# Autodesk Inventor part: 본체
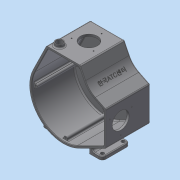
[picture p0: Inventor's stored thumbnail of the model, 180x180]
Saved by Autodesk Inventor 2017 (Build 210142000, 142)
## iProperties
Created: 2017-05
Part Number: 본체
Material: 알루미늄 6061
Document SubType Name: Modeling
Designer: mduedu
Density: 2.71 g/cm^3
Mass: 1345.72 g
Surface Area: 1824.08 cm^2
Volume: 496.576 cm^3
Appearance: 기본값
Author: mduedu
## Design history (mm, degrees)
sketch "스케치1"
  geometry: L1 (-71.801, 35.28)-(-40, 100); L2 (-40, 100)-(40, 100); L3 (40, 100)-(59.768, 59.768); L4 (59.768, 59.768)-(100, 40); L5 (100, 40)-(100, -40); L6 (100, -40)-(35.28, -71.801); A1 r 80 centre (0, 0) between (-71.801, 35.28) and (35.28, -71.801); 3 further points
  constraints: 12 end point, 4 tangent, 2 midpoint, 2 point on circle, 1 centre point, 1 coincident, 1 horizontal, 1 horizontal alignment, 1 perpendicular, 1 vertical alignment
  dimensions: "d0" = 160 diameter of A1; "d2" = 100 distance from line of L2 point (0, 0); "d3" = 100 distance from line of L5 point (0, 0); "d4" = 80 distance of L1.end L2.end; "d5" = 80 distance of L4.end L5.end
extrude "돌출1" new body sketch "스케치1" distance "d6" = 5; taper "d7" = 0 deg
fillet "모깎기1" dims "d8" = 50
sketch "스케치2"
  geometry: C1 r 22 at (0, 0); 1 further point
  constraints: 1 centre point, 1 coincident
  dimensions: "d9" = 44 diameter of C1
extrude "돌출2" join sketch "스케치2" distance "d10" = 22.5; taper "d11" = 0 deg
sketch "스케치3"
  geometry: C1 r 18.5 at (0, 0); 1 further point
  constraints: 1 centre point, 1 coincident
  dimensions: "d12" = 37 diameter of C1
extrude "돌출3" cut sketch "스케치3" distance "d13" = 9; taper "d14" = 0 deg
fillet "모깎기2" dims "d15" = 3
sketch "스케치4"
  geometry: L1 (35.28, -71.801)-(100, -40) reference; L2 (100, -40)-(100, 40) reference; L3 (100, 40)-(75.073, 52.248) reference; L4 (52.248, 75.073)-(40, 100) reference; L5 (40, 100)-(-40, 100) reference; L6 (-40, 100)-(-71.801, 35.28) reference; L7 (-36.886, 95)-(36.886, 95); L8 (36.886, 95)-(47.76, 72.868); L9 (72.868, 47.76)-(95, 36.886); L10 (95, 36.886)-(95, -36.886); L11 (95, -36.886)-(33.075, -67.313); L12 (-67.313, 33.075)-(-36.886, 95); C1 r 25 at (0, 0) reference; A1 r 50 centre (97.123, 97.123) between (52.248, 75.073) and (75.073, 52.248) reference; A2 r 80 centre (0, 0) between (-71.801, 35.28) and (35.28, -71.801) reference; A3 r 55 centre (97.123, 97.123) between (47.76, 72.868) and (72.868, 47.76); A4 r 75 centre (0, 0) between (-67.313, 33.075) and (33.075, -67.313); 1 further point
  constraints: 12 end point, 4 point on circle, 2 centre point, 7 other
  dimensions: "d16" = 5 distance between parallel lines of L7 L5
extrude "돌출4" join sketch "스케치4" distance "d17" = 100; taper "d18" = 0 deg
sketch "스케치5"
  geometry: L1 (80, 0)-(0, 0) reference; C1 r 20 at (40, -45); 2 further points
  constraints: 1 centre point, 1 midpoint, 1 vertical alignment
  dimensions: "d19" = 40 diameter of C1; "d21" = 45 distance from line of C1.centre L1
extrude "돌출5" cut sketch "스케치5" stored distance "d22" = 100; taper "d23" = 0 deg
sketch "스케치6"
  geometry: L1 (0, 0)-(0, -105) reference; L2 (80, -105)-(0, -105) reference; C1 r 9 at (14, -89); 1 further point
  constraints: 1 centre point
  dimensions: "d24" = 18 diameter of C1; "d26" = 14 distance from line of C1.centre L1; "d27" = 16 distance from line of C1.centre L2
extrude "돌출6" join sketch "스케치6" distance "d28" = 7; taper "d29" = 0 deg
hole "구멍1" diameter "d32" = 14; stored, may be unused: countersink angle "d36" = 90 deg, drill point angle "d38" = 118 deg; dims "d33" = 6, "d34" = 4, "d35" = 2, "d37" = 8, "d39" = 10, "d40" = 10
sketch "스케치7"
  geometry: L1 (-105, 0)-(-105, 80) reference; L2 (0, 0)-(0, 80) reference; C1 r 20 at (-70, 40); 2 further points
  constraints: 1 centre point, 1 horizontal alignment, 1 midpoint
  dimensions: "d41" = 40 diameter of C1; "d42" = 35 distance from line of C1.centre L1
extrude "돌출7" cut sketch "스케치7" stored distance "d43" = 7; taper "d44" = 0 deg
node "작업 평면1"
sketch "스케치8"
  geometry: L1 (47.76, 72.868)-(36.886, 95) reference; L2 (36.886, 95)-(-36.886, 95) reference; L3 (-36.886, 95)-(-67.313, 33.075) reference; L4 (33.075, -67.313)-(95, -36.886) reference; L5 (95, -36.886)-(95, 36.886) reference; L6 (95, 36.886)-(72.868, 47.76) reference; L7 (95, 36.886)-(95, -36.886) reference; L8 (-36.886, 95)-(36.886, 95) reference; L9 (36.886, 95)-(47.76, 72.868) reference; L10 (-71, 4)-(-74.893, 4); L11 (-71, -4)-(-74.893, -4); L12 (-4, -71)-(-4, -74.893); L13 (4, -71)-(4, -74.893); L14 (30.394, 91)-(30.394, 95); L15 (34.394, 87)-(40.817, 87); L16 (30.394, 95)-(36.886, 95); L17 (36.886, 95)-(37.984, 92.764); L18 (91, 30.394)-(95, 30.394); L19 (87, 34.394)-(87, 40.817); L20 (87, 40.817)-(95, 36.886); L21 (95, 36.886)-(95, 30.394); C1 r 25 at (0, 0) reference; A1 r 75 centre (0, 0) between (-67.313, 33.075) and (33.075, -67.313) reference; A2 r 55 centre (97.123, 97.123) between (47.76, 72.868) and (72.868, 47.76) reference; A3 r 4 centre (-71, 0) between (-71, 4) and (-71, -4); A4 r 4 centre (0, -71) between (-4, -71) and (4, -71); A5 r 4 centre (34.394, 91) between (30.394, 91) and (34.394, 87); A6 r 75 centre (0, 0) between (-67.313, 33.075) and (33.075, -67.313) reference; A7 r 4 centre (91, 34.394) between (91, 30.394) and (87, 34.394); 1 further point
  constraints: 24 end point, 17 point on circle, 14 tangent, 5 point on line, 4 centre point, 3 equal radius, 3 perpendicular, 3 vertical, 2 collinear, 2 horizontal, 1 horizontal alignment, 1 parallel, 1 vertical alignment
  dimensions: "d46" = 8 diameter of A3
extrude "돌출8" join sketch "스케치8" stored distance "d49" = 7; taper "d50" = 0 deg
node "작업 평면2"
sketch "스케치9"
  geometry: L1 (71.801, 0)-(71.801, 105) reference; L2 (71.801, 0)-(-35.28, 0) reference; L3 (-35.28, 0)-(-35.28, 105) reference; L4 (71.801, 105)-(-35.28, 105) reference; L5 (40, 0)-(40, 105) reference; L6 (71.801, 52.5)-(-35.28, 52.5); L7 (71.801, 20)-(40, 20); L8 (40, 20)-(40, 85); L9 (40, 85)-(71.801, 85); L10 (71.801, 85)-(71.801, 20); 1 further point
  constraints: 10 end point, 2 midpoint, 2 parallel, 2 point on line, 1 horizontal, 1 perpendicular, 1 other
  dimensions: "d52" = 20 distance between parallel lines of L7 L2
extrude "돌출9" join sketch "스케치9" distance "d53" = 8; taper "d54" = 0 deg
fillet "모깎기3" dims "d55" = 8
sketch "스케치10"
  geometry: C1 r 4 at (-63.801, -28); C2 r 4 at (-63.801, -77); A1 r 8 centre (-63.801, -28) between (-63.801, -20) and (-71.801, -28) reference; A2 r 8 centre (-63.801, -77) between (-71.801, -77) and (-63.801, -85) reference; 1 further point
  constraints: 2 centre point, 2 coincident, 1 equal radius
  dimensions: "d56" = 8 diameter of C1
extrude "돌출10" cut sketch "스케치10" stored distance "d57" = 50.5; taper "d58" = 0 deg
sketch "스케치11"
  geometry: L1 (-63.801, -20)-(-40, -20) reference; L2 (-40, -20)-(-40, -85) reference; L3 (-40, -85)-(-63.801, -85) reference; L4 (-71.801, -77)-(-71.801, -28) reference; L5 (71.801, -77)-(71.801, -28) reference; L6 (40, -85)-(63.801, -85) reference; L7 (40, -20)-(40, -85) reference; L8 (63.801, -20)-(40, -20) reference; L9 (-40, -85)-(-48, -85); L10 (-48, -85)-(-48, -20); L11 (-48, -20)-(-40, -20); L12 (-40, -20)-(-40, -85); L13 (40, -85)-(48, -85); L14 (48, -85)-(48, -20); L15 (48, -20)-(40, -20); L16 (40, -20)-(40, -85); C1 r 4 at (-63.801, -28) reference; C2 r 4 at (-63.801, -77) reference; C3 r 4 at (63.801, -28) reference; C4 r 4 at (63.801, -77) reference; A1 r 8 centre (-63.801, -28) between (-63.801, -20) and (-71.801, -28) reference; A2 r 8 centre (-63.801, -77) between (-71.801, -77) and (-63.801, -85) reference; A3 r 8 centre (63.801, -28) between (71.801, -28) and (63.801, -20) reference; A4 r 8 centre (63.801, -77) between (63.801, -85) and (71.801, -77) reference; 1 further point
  constraints: 16 end point, 4 parallel, 2 horizontal, 2 perpendicular, 2 point on line
  dimensions: "d59" = 8 distance of L10.end L11.end; "d61" = 8 distance of L14.end L15.end
extrude "돌출11" join sketch "스케치11" stored distance "d62" = 5; taper "d63" = 0 deg
fillet "모깎기4" dims "d64" = 5
fillet "모깎기5" dims "d65" = 2
fillet "모깎기6" dims "d66" = 2
fillet "모깎기8" dims "d68" = 2
fillet "모깎기9" dims "d70" = 3, "d101" = 1
fillet "모깎기10" dims "d71" = 3
fillet "모깎기11" dims "d72" = 3
fillet "모깎기12" dims "d73" = 3
fillet "모깎기13" dims "d76" = 3
chamfer "모따기1" distance "d77" = 0.5; stored, may be unused: second distance "d78" = 2, angle "d79" = 45 deg
chamfer "모따기2" distance "d87" = 1; stored, may be unused: second distance "d88" = 2, angle "d89" = 45 deg
chamfer "모따기3" distance "d90" = 1; stored, may be unused: second distance "d91" = 2, angle "d92" = 45 deg
sketch "스케치14"
  geometry: 3 further points
  constraints: 3 other
hole "구멍2" sketch "스케치14" at (-55.375, -40), (-3.414, -40), (-29.394, -85) diameter "d93" = 2.459; stored, may be unused: countersink angle "d97" = 90 deg, drill point angle "d99" = 0 deg; dims "d94" = 6, "d95" = 4, "d96" = 2, "d98" = 8
sketch "스케치15"
  geometry: 3 further points
  constraints: 3 other
hole "구멍4" sketch "스케치15" at (-55.981, -14.394), (-4.019, -14.394), (-30, -59.394) diameter "d102" = 2.459; stored, may be unused: countersink angle "d106" = 90 deg, drill point angle "d108" = 0 deg; dims "d103" = 6, "d104" = 4, "d105" = 2, "d107" = 8
sketch "스케치16"
  geometry: 4 further points
  constraints: 4 other
hole "구멍6" sketch "스케치16" at (0, -71), (91, 34.394), (34.394, 91), (-71, 0) diameter "d109" = 2.459; stored, may be unused: countersink angle "d113" = 90 deg, drill point angle "d115" = 120 deg; dims "d110" = 8.5, "d111" = 4, "d112" = 2, "d114" = 10
node "작업 평면4"
sketch "스케치17"
  geometry: 2 further points
  constraints: 1 horizontal alignment, 1 other
  dimensions: "d116" = 52.5 distance of point (0, 16.14) point (52.5, 16.14)
feature "엠보싱2" sketch "스케치17" dims "d117" = 0.5, "d118" = 0
node "솔리드1"
mirror "대칭1"
node "투영된 루프1"
node "투영된 루프2"
node "투영된 루프3"
node "투영된 루프4"
node "투영된 루프5"
other parameters: "d45" = 95
